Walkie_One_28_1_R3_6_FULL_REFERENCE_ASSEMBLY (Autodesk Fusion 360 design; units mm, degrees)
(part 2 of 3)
sketch "Sketch14" plane through (0, 0, -2) normal (0, 0, -1) x axis (-1, 0, 0)
  line L1 (10.455, -25.788) -> (10.455, -8.688)
  line L2 (-10.455, -25.788) -> (10.455, -25.788)
  line L3 (-10.455, -8.688) -> (-10.455, -25.788)
  line L4 (10.455, -8.688) -> (-10.455, -8.688)
  line L5 (15.947, 53.3392) -> (13.0996, 53.2792)
  line L6 (13.4186, 23) -> (16.2667, 23)
  line L7 (-13.7036, 52.7142) -> (-16.5511, 52.6542)
  line L8 (-16.2386, 23) -> (-13.3905, 23)
  line L9 (20, -67) -> (-20, -67)
  line L10 (32, 55) -> (32, -55)
  line L11 (-20, 67) -> (20, 67)
  line L12 (-32, -55) -> (-32, 55)
  circle C1 centre (0.0141, 38) radius 18
  circle C2 centre (0.0009, 14.35) radius 1.55
  circle C3 centre (-0.001, 61.6494) radius 1.5503
  arc A1 centre (0.0141, 38) radius 22.1167 clockwise from (15.947, 53.3392) to (16.2667, 23)
  arc A2 centre (0.0141, 38) radius 20.1167 clockwise from (13.0996, 53.2792) to (13.4186, 23)
  arc A3 centre (0.0141, 38) radius 20.1167 clockwise from (-13.3905, 23) to (-13.7036, 52.7142)
  arc A4 centre (0.0141, 38) radius 22.1167 clockwise from (-16.2386, 23) to (-16.5511, 52.6542)
  arc A5 centre (-20, -55) radius 12 clockwise from (-20, -67) to (-32, -55)
  arc A6 centre (20, -55) radius 12 clockwise from (32, -55) to (20, -67)
  arc A7 centre (20, 55) radius 12 clockwise from (20, 67) to (32, 55)
  arc A8 centre (-20, 55) radius 12 clockwise from (-32, 55) to (-20, 67)
  circle C4 centre (0, -47) radius 13.55
  circle C5 centre (0, 0) radius 2.4048
  circle C6 centre (22, -50) radius 3.0946
  circle C7 centre (-21.5, 24) radius 3
  circle C8 centre (-26.2206, 8.558) radius 3
  dimension "d195" diameter C7 = 6
  dimension "d196" diameter C8 = 6
extrude "Extrude13" add sketch "Sketch14" profile of C6 C7 C8 along normal blind 11
sketch "Sketch6" plane through (0, 0, -14.4) normal (0, 0, 1) x axis (1, 0, 0)
  line L1 (16.9755, 27.26) -> (26.9755, 27.26)
  line L2 (16.9755, 23.96) -> (16.9755, 27.26)
  line L3 (26.9755, 23.96) -> (16.9755, 23.96)
  line L4 (26.9755, 27.26) -> (26.9755, 23.96)
  line L5 (21.3, 23.96) -> (16.9755, 23.96)
  line L6 (21.3, 24.8) -> (21.3, 23.96)
  line L7 (16.9755, 24.8) -> (21.3, 24.8)
  line L8 (16.9755, 23.96) -> (16.9755, 24.8)
  point P4 (16.9755, 23.96)
  point P6 (16.9755, 23.96)
  horizontal L5
  vertical L6
  horizontal L7
  vertical L8
  coincident P4 P6
extrude "Extrude7" cut sketch "Sketch6" profile of L2 L3 L5 L6 L7 L8 against normal blind 1
sketch "Sketch7" plane through (0, 0, -22) normal (0, 0, 1) x axis (1, 0, 0)
  line L1 (22.6952, 6.5) -> (32, 6.5)
  line L2 (22.6952, 10.5) -> (22.6952, 6.5)
  line L3 (32, 10.5) -> (22.6952, 10.5)
  line L4 (32, 55) -> (32, 10.5)
  curve K1 (20, 67) -> (32, 55)
  line L5 (-20, 67) -> (20, 67)
  curve K2 (-32, 55) -> (-20, 67)
  line L6 (-32, -55) -> (-32, 55)
  curve K3 (-20, -67) -> (-32, -55)
  line L7 (20, -67) -> (-20, -67)
  curve K4 (32, -55) -> (20, -67)
  line L8 (32, 6.5) -> (32, -55)
  line L9 (-26.9755, -50.04) -> (-26.9755, -58.04)
  line L10 (-16.9755, -50.04) -> (-26.9755, -50.04)
  line L11 (-16.9755, -58.04) -> (-16.9755, -50.04)
  line L12 (-26.9755, -58.04) -> (-16.9755, -58.04)
  line L13 (26.9755, 31.96) -> (16.9755, 31.96)
  line L14 (26.9755, 23.96) -> (26.9755, 31.96)
  line L15 (16.9755, 23.96) -> (26.9755, 23.96)
  line L16 (16.9755, 31.96) -> (16.9755, 23.96)
  line L17 (20, 73) -> (-20, 73)
  line L18 (-20, -73) -> (20, -73)
  line L19 (-38, 55) -> (-38, -55)
  line L20 (38, -55) -> (38, -15.5)
  line L21 (31, 66) -> (-31, 66)
  line L22 (31, -66) -> (31, 66)
  line L23 (-31, -66) -> (31, -66)
  line L24 (-31, 66) -> (-31, -66)
  line L25 (38, 32.5) -> (38, 55)
  circle C1 centre (-31, 66) radius 1.5
  circle C2 centre (31, 66) radius 1.5
  circle C3 centre (31, -66) radius 1.5
  circle C4 centre (-31, -66) radius 1.5
  point P22 (-31, 66)
  point P31 (-31, 66)
  point P32 (31, 66)
  point P35 (31, 66)
  point P33 (31, -66)
  point P36 (31, -66)
  point P34 (-31, -66)
  point P37 (-31, -66)
  horizontal L21
  vertical L22
  horizontal L23
  vertical L24
  coincident P22 P31
  coincident P32 P35
  coincident P33 P36
  coincident P34 P37
  dimension "d201" diameter C1 = 3
  dimension "d202" distance P22 L17 = 7
  dimension "d203" distance P22 L19 = 7
  dimension "d210" diameter C2 = 3
  dimension "d211" diameter C4 = 3
  dimension "d212" diameter C3 = 3
  dimension "d225" distance L22 L25 = 7
  dimension "d226" distance L18 L23 = 7
position "Position6"
sketch "Sketch6" plane through (-41.9, 0, 0) normal (-1, 0, 0) x axis (0, 0, 1)
  line L1 (-12.1, 39) -> (-11.9, 39)
  line L2 (-18, -9.1) -> (-18, 33.1)
  line L3 (-11.9, -15) -> (-12.1, -15)
  line L4 (-6, 33.1) -> (-6, -9.1)
  line L5 (-12.1, 39) -> (-11.9, 39)
  line L6 (-18, -9.1) -> (-18, 33.1)
  line L7 (-11.9, -15) -> (-12.1, -15)
  line L8 (-6, 33.1) -> (-6, -9.1)
  line L9 (-18.3, -9.1) -> (-18.3, 33.1)
  line L10 (-11.9, -15.3) -> (-12.1, -15.3)
  line L11 (-5.7, 33.1) -> (-5.7, -9.1)
  line L12 (-12.1, 39.3) -> (-11.9, 39.3)
  arc A1 centre (-11.9, 33.1) radius 5.9 clockwise from (-11.9, 39) to (-6, 33.1)
  arc A2 centre (-12.1, 33.1) radius 5.9 clockwise from (-18, 33.1) to (-12.1, 39)
  arc A3 centre (-12.1, -9.1) radius 5.9 clockwise from (-12.1, -15) to (-18, -9.1)
  arc A4 centre (-11.9, -9.1) radius 5.9 clockwise from (-6, -9.1) to (-11.9, -15)
  arc A5 centre (-12.1, 33.1) radius 5.9 clockwise from (-18, 33.1) to (-12.1, 39)
  arc A6 centre (-12.1, -9.1) radius 5.9 clockwise from (-12.1, -15) to (-18, -9.1)
  arc A7 centre (-11.9, -9.1) radius 5.9 clockwise from (-6, -9.1) to (-11.9, -15)
  arc A8 centre (-11.9, 33.1) radius 5.9 clockwise from (-11.9, 39) to (-6, 33.1)
  arc A9 centre (-12.1, 33.1) radius 6.2 clockwise from (-18.3, 33.1) to (-12.1, 39.3)
  arc A10 centre (-12.1, -9.1) radius 6.2 clockwise from (-12.1, -15.3) to (-18.3, -9.1)
  arc A11 centre (-11.9, -9.1) radius 6.2 clockwise from (-5.7, -9.1) to (-11.9, -15.3)
  arc A12 centre (-11.9, 33.1) radius 6.2 clockwise from (-11.9, 39.3) to (-5.7, 33.1)
  dimension "d204" distance L4 = 0
  dimension "d205" = 0.3
extrude "Extrude8" cut sketch "Sketch6" against normal blind 6
extrude "Extrude9" cut sketch "Sketch7" profile of K1 K2 K3 K4 C1 C2 C3 C4 against normal blind 10 and along normal blind 5
sketch "Sketch8" plane through (0, 0, -22) normal (0, 0, 1) x axis (1, 0, 0)
  circle C1 centre (-31, 66) radius 5.5
  circle C2 centre (31, 66) radius 5.5
  circle C3 centre (31, -66) radius 1.5
  circle C4 centre (-31, -66) radius 1.5
  circle C5 centre (-31, -66) radius 5.5
  circle C6 centre (31, -66) radius 5.5
  circle C7 centre (-31, 66) radius 1.5
  circle C8 centre (31, 66) radius 1.5
  circle C9 centre (-31, -66) radius 1.5
  circle C10 centre (31, -66) radius 1.5
  concentric C4 C5
  concentric C3 C6
  concentric C1 C7
  concentric C2 C8
  concentric C5 C9
  concentric C6 C10
  dimension "d217" diameter C1 = 11
  dimension "d218" diameter C2 = 11
  dimension "d219" diameter C6 = 11
  dimension "d220" diameter C5 = 11
  dimension "d221" diameter C7 = 3
  dimension "d222" diameter C8 = 3
  dimension "d223" diameter C9 = 3
  dimension "d224" diameter C10 = 3
extrude "Extrude10" add sketch "Sketch8" along normal blind 10
delete_face "DeleteFace2"
sketch "Sketch9" plane through (0, 0, -22) normal (0, 0, -1) x axis (-1, 0, 0)
  curve K1 (-31.1274, 69.9946) -> (-32.4946, 68.6274)
  arc A1 centre (-31, 66) radius 1.5 clockwise from (-31.8292, 67.25) to (-30.1708, 67.25)
  circle C1 centre (31, -66) radius 2.75
  circle C2 centre (-31, -66) radius 2.75
  circle C3 centre (-31, 66) radius 2.75
  circle C4 centre (31, 66) radius 2.75
  arc A2 centre (-31, 68.5) radius 1.5 clockwise from (-31.8292, 67.25) to (-32.4946, 68.6274)
  arc A3 centre (-31, 68.5) radius 1.5 clockwise from (-31.1274, 69.9946) to (-30.1708, 67.25)
  point P7 (-31, -66)
  point P10 (-31, -66)
  point P9 (-31, 66)
  point P11 (-31, 66)
  point P8 (31, 66)
  point P12 (31, 66)
  coincident P7 P10
  coincident P9 P11
  coincident P8 P12
  dimension "d229" diameter C1 = 5.5
  dimension "d230" diameter C2 = 5.5
  dimension "d231" diameter C3 = 5.5
  dimension "d232" diameter C4 = 5.5
extrude "Extrude11" cut sketch "Sketch9" profile of K1 A1 C1 C2 C3 C4 along normal blind 6 and against normal blind 2
sketch "Sketch15" plane through (0, 0, -2) normal (0, 0, -1) x axis (-1, 0, 0)
  line L1 (20, -67) -> (-20, -67)
  line L2 (32, 55) -> (32, -55)
  line L3 (-20, 67) -> (20, 67)
  line L4 (-32, -55) -> (-32, 55)
  line L5 (-13.7036, 52.7142) -> (-16.5511, 52.6542)
  line L6 (-16.2386, 23) -> (-13.3905, 23)
  line L7 (15.947, 53.3392) -> (13.0996, 53.2792)
  line L8 (13.4186, 23) -> (16.2667, 23)
  line L9 (10.455, -25.788) -> (10.455, -8.688)
  line L10 (-10.455, -25.788) -> (10.455, -25.788)
  line L11 (-10.455, -8.688) -> (-10.455, -25.788)
  line L12 (10.455, -8.688) -> (-10.455, -8.688)
  curve K1 (-33.7293, 65.6634) -> (-33.7293, 65.6634)
  curve K2 (28.5839, 67.3134) -> (28.5839, 67.3134)
  curve K3 (-33.2911, -64.479) -> (-33.2911, -64.479)
  curve K4 (28.2521, -65.8917) -> (28.2521, -65.8917)
  circle C1 centre (-26.2206, 8.558) radius 3
  circle C2 centre (0, 0) radius 2.4048
  circle C3 centre (0, -47) radius 13.55
  arc A1 centre (-20, -55) radius 12 clockwise from (-20, -67) to (-32, -55)
  arc A2 centre (20, -55) radius 12 clockwise from (32, -55) to (20, -67)
  arc A3 centre (20, 55) radius 12 clockwise from (20, 67) to (32, 55)
  arc A4 centre (-20, 55) radius 12 clockwise from (-32, 55) to (-20, 67)
  arc A5 centre (0.0141, 38) radius 20.1167 clockwise from (-13.3905, 23) to (-13.7036, 52.7142)
  arc A6 centre (0.0141, 38) radius 22.1167 clockwise from (-16.2386, 23) to (-16.5511, 52.6542)
  arc A7 centre (0.0141, 38) radius 22.1167 clockwise from (15.947, 53.3392) to (16.2667, 23)
  arc A8 centre (0.0141, 38) radius 20.1167 clockwise from (13.0996, 53.2792) to (13.4186, 23)
  circle C4 centre (-0.001, 61.6494) radius 1.5503
  circle C5 centre (0.0009, 14.35) radius 1.55
  circle C6 centre (0.0141, 38) radius 18
  circle C7 centre (-21.5, 24) radius 3
  circle C8 centre (22, -50) radius 3.0946
  circle C9 centre (-31, 66) radius 3.5
  circle C10 centre (31, 66) radius 3.5
  circle C11 centre (-31, -66) radius 3.5
  circle C12 centre (31, -66) radius 3.5
  circle C13 centre (-31, 66) radius 1
  circle C14 centre (31, 66) radius 1
  circle C15 centre (-31, -66) radius 1
  circle C16 centre (31, -66) radius 1
  concentric C9 C13
  concentric C10 C14
  concentric C11 C15
  concentric C12 C16
  dimension "d237" diameter C9 = 7
  dimension "d238" diameter C10 = 7
  dimension "d239" diameter C11 = 7
  dimension "d240" diameter C12 = 7
  dimension "d241" diameter C13 = 2
  dimension "d242" diameter C14 = 2
  dimension "d243" diameter C15 = 2
  dimension "d244" diameter C16 = 2
extrude "Extrude15" add sketch "Sketch15" profile of K1 K2 K3 K4 C9 C10 C11 C12 C13 C14 C15 C16 along normal blind 10
delete_face "DeleteFace1"
sketch "Sketch11" plane through (0, 0, -12) normal (0, 0, 1) x axis (1, 0, 0)
  line L1 (-40, 39.3) -> (-40, 55)
  line L2 (-38, 55) -> (-38, 39.3)
  line L3 (38, 32.5) -> (38, 55)
  line L4 (40, 55) -> (40, 32.5)
  line L5 (-35.1621, -62.4046) -> (-34.285, -64.2974)
  line L6 (-26.9184, -69.6865) -> (-29.2974, -69.285)
  line L7 (26.9184, -69.6865) -> (29.2974, -69.285)
  line L8 (35.1621, -62.4046) -> (34.285, -64.2974)
  line L9 (27.3105, 70.0789) -> (29.2974, 69.285)
  line L10 (35.0789, 62.3105) -> (34.285, 64.2974)
  line L11 (-27.3105, 70.0789) -> (-29.2974, 69.285)
  line L12 (-35.0789, 62.3105) -> (-34.285, 64.2974)
  line L13 (-20, 75) -> (20, 75)
  line L14 (-38, 39.3) -> (-40, 39.3)
  line L15 (20, 73) -> (-20, 73)
  line L16 (40, 32.5) -> (38, 32.5)
  arc A1 centre (-31, 66) radius 5.5 clockwise from (-28.4692, 70.8831) to (-35.8831, 63.4692)
  arc A2 centre (31, 66) radius 5.5 clockwise from (35.8831, 63.4692) to (28.4692, 70.8831)
  arc A3 centre (31, -66) radius 5.5 clockwise from (28.4692, -70.8831) to (35.8831, -63.4692)
  arc A4 centre (-31, -66) radius 5.5 clockwise from (-35.8831, -63.4692) to (-28.4692, -70.8831)
  arc A5 centre (31, -66) radius 3.7 clockwise from (29.2974, -69.285) to (34.285, -64.2974)
  arc A6 centre (-31, -66) radius 3.7 clockwise from (-34.285, -64.2974) to (-29.2974, -69.285)
  circle C1 centre (-31, 66) radius 1.5
  arc A7 centre (20, 55) radius 20 clockwise from (20, 75) to (40, 55)
  arc A8 centre (-20, 55) radius 20 clockwise from (-40, 55) to (-20, 75)
  arc A9 centre (-20, 55) radius 18 clockwise from (-38, 55) to (-35.8831, 63.4692)
  arc A10 centre (-31, 66) radius 5.5 clockwise from (-28.4692, 70.8831) to (-35.8831, 63.4692)
  arc A11 centre (-20, 55) radius 18 clockwise from (-28.4692, 70.8831) to (-20, 73)
  arc A12 centre (20, 55) radius 18 clockwise from (20, 73) to (28.4692, 70.8831)
  arc A13 centre (31, 66) radius 5.5 clockwise from (35.8831, 63.4692) to (28.4692, 70.8831)
  arc A14 centre (20, 55) radius 18 clockwise from (35.8831, 63.4692) to (38, 55)
  circle C2 centre (31, 66) radius 1.5
  arc A15 centre (31, 66) radius 3.7 clockwise from (34.285, 64.2974) to (29.2974, 69.285)
  arc A16 centre (-31, 66) radius 3.7 clockwise from (-29.2974, 69.285) to (-34.285, 64.2974)
  point P32 (-26.9184, -69.6865)
  point P33 (-35.1621, -62.4046)
  point P38 (35.1621, -62.4046)
  point P39 (26.9184, -69.6865)
  coincident A4 P32
  coincident A4 P33
  coincident A3 P38
  coincident A3 P39
  dimension "d250" = -1.8
  dimension "d251" = -1.8
  dimension "d398" = -1.8
  dimension "d399" = -1.8
extrude "Extrude12" add sketch "Sketch11" profile of A1 A2 A3 A4 A5 A6 L5 L6 L7 L8 L9 L10 L11 L12 along normal blind 2
fillet "Fillet3" radius 0.5
offset_faces "OffsetFaces1" distance 2
offset_faces "OffsetFaces2" distance 2
fillet "Fillet3" radius 2
sketch "Sketch16" plane through (0, 0, -5) normal (0, 0, -1) x axis (-1, 0, 0)
  line L1 (-8.455, -23.788) -> (8.455, -23.788)
  line L2 (-8.455, -10.688) -> (-8.455, -23.788)
  line L3 (8.455, -10.688) -> (-8.455, -10.688)
  line L4 (8.455, -23.788) -> (8.455, -10.688)
  line L5 (-10.455, -8.688) -> (10.455, -8.688)
  line L6 (-12.455, -23.788) -> (-12.455, -10.688)
  line L7 (10.455, -25.788) -> (-10.455, -25.788)
  line L8 (12.455, -10.688) -> (12.455, -23.788)
  arc A1 centre (10.455, -10.688) radius 2 clockwise from (10.455, -8.688) to (12.455, -10.688)
  arc A2 centre (-10.455, -10.688) radius 2 clockwise from (-12.455, -10.688) to (-10.455, -8.688)
  arc A3 centre (-10.455, -23.788) radius 2 clockwise from (-10.455, -25.788) to (-12.455, -23.788)
  arc A4 centre (10.455, -23.788) radius 2 clockwise from (12.455, -23.788) to (10.455, -25.788)
  circle C1 centre (-9.955, -17.238) radius 1
  circle C2 centre (9.955, -17.238) radius 1
  point P18 (-9.955, -17.238)
  point P19 (9.955, -17.238)
  dimension "d260" diameter C1 = 2
  dimension "d261" distance L2 P18 = 1.5
  dimension "d262" diameter C2 = 2
  dimension "d263" distance L4 P19 = 1.5
extrude "Extrude16" cut sketch "Sketch16" profile of C1 C2 against normal blind 3
position "Position7"
sketch "Sketch7" plane through (0, 0, -2) normal (0, 0, -1) x axis (-1, 0, 0)
  line L1 (20, -67) -> (-20, -67)
  line L2 (32, 55) -> (32, -55)
  line L3 (-20, 67) -> (20, 67)
  line L4 (-32, -55) -> (-32, 55)
  line L5 (-13.7036, 52.7142) -> (-16.5511, 52.6542)
  line L6 (-16.2386, 23) -> (-13.3905, 23)
  line L7 (15.947, 53.3392) -> (13.0996, 53.2792)
  line L8 (13.4186, 23) -> (16.2667, 23)
  line L9 (12.455, -23.788) -> (12.455, -10.688)
  line L10 (-10.455, -25.788) -> (10.455, -25.788)
  line L11 (-12.455, -10.688) -> (-12.455, -23.788)
  line L12 (10.455, -8.688) -> (-10.455, -8.688)
  line L13 (18.542, -42) -> (-18.5381, -42)
  line L14 (18.542, -52) -> (18.542, -42)
  line L15 (-18.5381, -52) -> (18.542, -52)
  line L16 (-18.5381, -42) -> (-18.5381, -52)
  line L17 (-13.5381, -55) -> (-13.5381, -46.4331)
  line L18 (13.542, -56) -> (13.542, -47.467)
  circle C1 centre (-26.2206, 8.558) radius 3
  circle C2 centre (0, 0) radius 2.4048
  circle C3 centre (0, -47) radius 13.55
  arc A1 centre (-20, -55) radius 12 clockwise from (-20, -67) to (-32, -55)
  arc A2 centre (20, -55) radius 12 clockwise from (32, -55) to (20, -67)
  arc A3 centre (20, 55) radius 12 clockwise from (20, 67) to (32, 55)
  arc A4 centre (-20, 55) radius 12 clockwise from (-32, 55) to (-20, 67)
  arc A5 centre (0.0141, 38) radius 20.1167 clockwise from (-13.3905, 23) to (-13.7036, 52.7142)
  arc A6 centre (0.0141, 38) radius 22.1167 clockwise from (-16.2386, 23) to (-16.5511, 52.6542)
  arc A7 centre (0.0141, 38) radius 22.1167 clockwise from (15.947, 53.3392) to (16.2667, 23)
  arc A8 centre (0.0141, 38) radius 20.1167 clockwise from (13.0996, 53.2792) to (13.4186, 23)
  circle C4 centre (-0.001, 61.6494) radius 1.5503
  circle C5 centre (0.0009, 14.35) radius 1.55
  circle C6 centre (0.0141, 38) radius 18
  arc A9 centre (10.455, -23.788) radius 2 clockwise from (12.455, -23.788) to (10.455, -25.788)
  arc A10 centre (-10.455, -23.788) radius 2 clockwise from (-10.455, -25.788) to (-12.455, -23.788)
  arc A11 centre (-10.455, -10.688) radius 2 clockwise from (-12.455, -10.688) to (-10.455, -8.688)
  arc A12 centre (10.455, -10.688) radius 2 clockwise from (10.455, -8.688) to (12.455, -10.688)
  circle C7 centre (-21.5, 24) radius 3
  circle C8 centre (22, -50) radius 3.0946
  point P46 (-13.5381, -46.4331)
  point P48 (13.542, -47.467)
  horizontal L13
  vertical L14
  horizontal L15
  vertical L16
  coincident C3 P46
  perpendicular L15 L17
  coincident C3 P48
  perpendicular L15 L18
  dimension "d266" distance L16 L17 = 5
  dimension "d267" distance L14 L18 = 5
sketch "Sketch17" plane through (0, 0, -2) normal (0, 0, -1) x axis (-1, 0, 0)
  line L1 (20, -67) -> (-20, -67)
  line L2 (32, 55) -> (32, -55)
  line L3 (-20, 67) -> (20, 67)
  line L4 (-32, -55) -> (-32, 55)
  line L5 (-13.7036, 52.7142) -> (-16.5511, 52.6542)
  line L6 (-16.2386, 23) -> (-13.3905, 23)
  line L7 (15.947, 53.3392) -> (13.0996, 53.2792)
  line L8 (13.4186, 23) -> (16.2667, 23)
  line L9 (12.455, -23.788) -> (12.455, -10.688)
  line L10 (-10.455, -25.788) -> (10.455, -25.788)
  line L11 (-12.455, -10.688) -> (-12.455, -23.788)
  line L12 (10.455, -8.688) -> (-10.455, -8.688)
  line L13 (-18.5, -56.5) -> (18.5, -56.5)
  line L14 (-18.5, -37.5) -> (-18.5, -56.5)
  line L15 (18.5, -37.5) -> (-18.5, -37.5)
  line L16 (18.5, -56.5) -> (18.5, -37.5)
  line L17 (-18.5, -37.5) -> (18.5, -56.5)
  line L18 (18.5, -37.5) -> (-18.5, -56.5)
  circle C1 centre (-26.2206, 8.558) radius 3
  circle C2 centre (0, 0) radius 2.4048
  circle C3 centre (0, -47) radius 13.55
  arc A1 centre (-20, -55) radius 12 clockwise from (-20, -67) to (-32, -55)
  arc A2 centre (20, -55) radius 12 clockwise from (32, -55) to (20, -67)
  arc A3 centre (20, 55) radius 12 clockwise from (20, 67) to (32, 55)
  arc A4 centre (-20, 55) radius 12 clockwise from (-32, 55) to (-20, 67)
  arc A5 centre (0.0141, 38) radius 20.1167 clockwise from (-13.3905, 23) to (-13.7036, 52.7142)
  arc A6 centre (0.0141, 38) radius 22.1167 clockwise from (-16.2386, 23) to (-16.5511, 52.6542)
  arc A7 centre (0.0141, 38) radius 22.1167 clockwise from (15.947, 53.3392) to (16.2667, 23)
  arc A8 centre (0.0141, 38) radius 20.1167 clockwise from (13.0996, 53.2792) to (13.4186, 23)
  circle C4 centre (-0.001, 61.6494) radius 1.5503
  circle C5 centre (0.0009, 14.35) radius 1.55
  circle C6 centre (0.0141, 38) radius 18
  arc A9 centre (10.455, -23.788) radius 2 clockwise from (12.455, -23.788) to (10.455, -25.788)
  arc A10 centre (-10.455, -23.788) radius 2 clockwise from (-10.455, -25.788) to (-12.455, -23.788)
  arc A11 centre (-10.455, -10.688) radius 2 clockwise from (-12.455, -10.688) to (-10.455, -8.688)
  arc A12 centre (10.455, -10.688) radius 2 clockwise from (10.455, -8.688) to (12.455, -10.688)
  circle C7 centre (-21.5, 24) radius 3
  circle C8 centre (22, -50) radius 3.0946
  circle C9 centre (-16, -54) radius 1
  circle C10 centre (-16, -54) radius 3.25
  circle C11 centre (16, -40) radius 1
  circle C12 centre (16, -40) radius 3.25
  point P46 (0, -47)
  point P4 (0, -47)
  point P44 (-18.5, -37.5)
  point P45 (18.5, -37.5)
  point P43 (-18.5, -56.5)
  point P48 (-16, -54)
  point P49 (16, -40)
  horizontal L13
  perpendicular L13 L14
  parallel L13 L15
  parallel L14 L16
  coincident L17 P46
  coincident L18 P46
  coincident P4 P46
  concentric C9 C10
  concentric C11 C12
  dimension "d268" distance P44 P45 = 37
  dimension "d269" distance P43 P44 = 19
  dimension "d270" diameter C9 = 2
  dimension "d271" diameter C10 = 6.5
  dimension "d272" distance L14 P48 = 2.5
  dimension "d274" diameter C11 = 2
  dimension "d275" diameter C12 = 6.5
  dimension "d277" distance L16 P49 = 2.5
  dimension "d278" distance L15 P49 = 2.5
  dimension "d279" distance L13 P48 = 2.5
extrude "Extrude17" add sketch "Sketch17" profile of L13 L14 L15 L16 C9 C10 C11 C12 along normal blind 5
sketch "Sketch8" plane through (0, 0, -7) normal (0, 0, -1) x axis (-1, 0, 0)
  line L1 (-21, -59) -> (-9, -59)
  line L2 (-21, -42) -> (-21, -59)
  line L3 (18.8, -35) -> (9, -35)
  line L4 (-6.9857, -42) -> (6, -51.5684)
  line L5 (9, -42) -> (9, -35)
  line L6 (-21, -42) -> (9, -42)
  line L7 (6, -41) -> (6, -53)
  line L8 (-9, -51) -> (-9, -59)
  line L9 (15, -51) -> (-9, -51)
  line L10 (-6, -53) -> (-6, -41)
  line L11 (21, -35) -> (18.8, -35)
  line L12 (21, -45) -> (21, -35)
  line L13 (18.8, -45) -> (21, -45)
  line L14 (15, -51) -> (18.8, -45)
  circle C1 centre (-16, -54) radius 1
  circle C2 centre (-16, -54) radius 3.25
  circle C3 centre (16, -40) radius 1
  point P5 (-0.2, -47)
  point P16 (-6.9857, -42)
  point P17 (6, -51.5684)
  point P6 (16, -40)
  point P18 (21, -35)
  point P19 (21, -45)
  point P2 (-16, -54)
  horizontal L1
  perpendicular L1 L2
  parallel L1 L3
  coincident L4 P5
  vertical L5
  horizontal L6
  vertical L8
  horizontal L9
  coincident L6 P16
  coincident L7 P17
  horizontal L11
  vertical L12
  horizontal L13
  dimension "d282" distance L3 P6 = 5
  dimension "d284" distance L5 L7 = 3
  dimension "d285" distance L8 L10 = 3
  dimension "d288" distance P18 P19 = 10
  dimension "d289" distance P2 L1 = 5
  dimension "d290" distance P2 L2 = 5
  dimension "d291" distance P6 L12 = 5
extrude "Extrude1" new body sketch "Sketch8" profile of C1 C2 L1 L2 L3 C3 L5 L6 L7 L8 L9 L10 along normal blind 4
fillet "Fillet1" radius 2
sketch "Sketch1" plane through (0, 0, -11) normal (0, 0, -1) x axis (-1, 0, 0)
  line L1 (-21, -57) -> (-21, -44)
  line L2 (-11, -59) -> (-19, -59)
  line L3 (-9, -53) -> (-9, -57)
  line L4 (13.8993, -51) -> (-7, -51)
  line L5 (18.8, -45) -> (15.5889, -50.0701)
  line L6 (19, -45) -> (18.8, -45)
  line L7 (21, -37) -> (21, -43)
  line L8 (11, -35) -> (19, -35)
  line L9 (9, -40) -> (9, -37)
  line L10 (-19, -42) -> (7, -42)
  arc A1 centre (-19, -44) radius 2 clockwise from (-21, -44) to (-19, -42)
  arc A2 centre (-19, -57) radius 2 clockwise from (-19, -59) to (-21, -57)
  arc A3 centre (-11, -57) radius 2 clockwise from (-9, -57) to (-11, -59)
  arc A4 centre (-7, -53) radius 2 clockwise from (-9, -53) to (-7, -51)
  arc A5 centre (13.8993, -49) radius 2 clockwise from (15.5889, -50.0701) to (13.8993, -51)
  arc A6 centre (19, -43) radius 2 clockwise from (21, -43) to (19, -45)
  arc A7 centre (19, -37) radius 2 clockwise from (19, -35) to (21, -37)
  arc A8 centre (11, -37) radius 2 clockwise from (9, -37) to (11, -35)
  arc A9 centre (7, -40) radius 2 clockwise from (9, -40) to (7, -42)
  circle C1 centre (-16, -54) radius 3.25
  circle C2 centre (16, -40) radius 3.25
  circle C3 centre (-16, -54) radius 1.5
  circle C4 centre (16, -40) radius 1.5
  concentric C1 C3
  concentric C2 C4
  dimension "d294" diameter C4 = 3
  dimension "d295" diameter C3 = 3
extrude "Extrude2" cut sketch "Sketch1" profile of C3 C4 against normal blind 7
sketch "Sketch2" plane through (0, 0, -11) normal (0, 0, -1) x axis (-1, 0, 0)
  line L1 (-21, -57) -> (-21, -44)
  line L2 (-11, -59) -> (-19, -59)
  line L3 (-9, -53) -> (-9, -57)
  line L4 (13.8993, -51) -> (-7, -51)
  line L5 (18.8, -45) -> (15.5889, -50.0701)
  line L6 (19, -45) -> (18.8, -45)
  line L7 (21, -37) -> (21, -43)
  line L8 (11, -35) -> (19, -35)
  line L9 (9, -40) -> (9, -37)
  line L10 (-19, -42) -> (7, -42)
  circle C1 centre (-16, -54) radius 1.5
  circle C2 centre (16, -40) radius 1.5
  arc A1 centre (-19, -44) radius 2 clockwise from (-21, -44) to (-19, -42)
  arc A2 centre (-19, -57) radius 2 clockwise from (-19, -59) to (-21, -57)
  arc A3 centre (-11, -57) radius 2 clockwise from (-9, -57) to (-11, -59)
  arc A4 centre (-7, -53) radius 2 clockwise from (-9, -53) to (-7, -51)
  arc A5 centre (13.8993, -49) radius 2 clockwise from (15.5889, -50.0701) to (13.8993, -51)
  arc A6 centre (19, -43) radius 2 clockwise from (21, -43) to (19, -45)
  arc A7 centre (19, -37) radius 2 clockwise from (19, -35) to (21, -37)
  arc A8 centre (11, -37) radius 2 clockwise from (9, -37) to (11, -35)
  arc A9 centre (7, -40) radius 2 clockwise from (9, -40) to (7, -42)
  circle C3 centre (-16, -54) radius 2.75
  circle C4 centre (16, -40) radius 2.75
  concentric C1 C3
  concentric C2 C4
  dimension "d298" diameter C4 = 5.5
  dimension "d299" diameter C3 = 5.5
extrude "Extrude3" cut sketch "Sketch2" profile of C1 C2 C3 C4 against normal blind 2.5
sketch "Sketch9" plane through (0, 0, -2) normal (0, 0, -1) x axis (-1, 0, 0)
  line L1 (20, -67) -> (-20, -67)
  line L2 (32, 55) -> (32, -55)
  line L3 (-20, 67) -> (20, 67)
  line L4 (-32, -55) -> (-32, 55)
  line L5 (-13.7036, 52.7142) -> (-16.5511, 52.6542)
  line L6 (-16.2386, 23) -> (-13.3905, 23)
  line L7 (15.947, 53.3392) -> (13.0996, 53.2792)
  line L8 (13.4186, 23) -> (16.2667, 23)
  line L9 (12.455, -23.788) -> (12.455, -10.688)
  line L10 (-10.455, -25.788) -> (10.455, -25.788)
  line L11 (-12.455, -10.688) -> (-12.455, -23.788)
  line L12 (10.455, -8.688) -> (-10.455, -8.688)
  circle C1 centre (-16, -54) radius 3.25
  circle C2 centre (-26.2206, 8.558) radius 3
  circle C3 centre (0, 0) radius 2.4048
  circle C4 centre (0, -47) radius 13.55
  arc A1 centre (-20, -55) radius 12 clockwise from (-20, -67) to (-32, -55)
  arc A2 centre (20, -55) radius 12 clockwise from (32, -55) to (20, -67)
  arc A3 centre (20, 55) radius 12 clockwise from (20, 67) to (32, 55)
  arc A4 centre (-20, 55) radius 12 clockwise from (-32, 55) to (-20, 67)
  arc A5 centre (0.0141, 38) radius 20.1167 clockwise from (-13.3905, 23) to (-13.7036, 52.7142)
  arc A6 centre (0.0141, 38) radius 22.1167 clockwise from (-16.2386, 23) to (-16.5511, 52.6542)
  arc A7 centre (0.0141, 38) radius 22.1167 clockwise from (15.947, 53.3392) to (16.2667, 23)
  arc A8 centre (0.0141, 38) radius 20.1167 clockwise from (13.0996, 53.2792) to (13.4186, 23)
  circle C5 centre (-0.001, 61.6494) radius 1.5503
  circle C6 centre (0.0009, 14.35) radius 1.55
  circle C7 centre (0.0141, 38) radius 18
  arc A9 centre (10.455, -23.788) radius 2 clockwise from (12.455, -23.788) to (10.455, -25.788)
  arc A10 centre (-10.455, -23.788) radius 2 clockwise from (-10.455, -25.788) to (-12.455, -23.788)
  arc A11 centre (-10.455, -10.688) radius 2 clockwise from (-12.455, -10.688) to (-10.455, -8.688)
  arc A12 centre (10.455, -10.688) radius 2 clockwise from (10.455, -8.688) to (12.455, -10.688)
  circle C8 centre (-21.5, 24) radius 3
  circle C9 centre (22, -50) radius 3.0946
  circle C10 centre (16, -40) radius 3.25
sketch "Sketch18" plane through (0, 0, -2) normal (0, 0, -1) x axis (-1, 0, 0)
  line L1 (20, -67) -> (-20, -67)
  line L2 (32, 55) -> (32, -55)
  line L3 (-20, 67) -> (20, 67)
  line L4 (-32, -55) -> (-32, 55)
  line L5 (-13.7036, 52.7142) -> (-16.5511, 52.6542)
  line L6 (-16.2386, 23) -> (-13.3905, 23)
  line L7 (15.947, 53.3392) -> (13.0996, 53.2792)
  line L8 (13.4186, 23) -> (16.2667, 23)
  line L9 (12.455, -23.788) -> (12.455, -10.688)
  line L10 (-10.455, -25.788) -> (10.455, -25.788)
  line L11 (-12.455, -10.688) -> (-12.455, -23.788)
  line L12 (10.455, -8.688) -> (-10.455, -8.688)
  line L13 (-26.7827, 25) -> (-37.7827, 25)
  line L14 (-26.7827, 21) -> (-26.7827, 25)
  line L15 (-37.7827, 21) -> (-26.7827, 21)
  line L16 (-37.7827, 25) -> (-37.7827, 21)
  line L17 (-33.9653, -8) -> (-33.9653, 19)
  line L18 (-50.0702, 5.5) -> (-34, 5.5)
  line L19 (-37.7827, -4) -> (-26.671, -4)
  line L20 (-37.7827, -8) -> (-37.7827, -4)
  line L21 (-26.7827, -8) -> (-37.7827, -8)
  line L22 (-26.671, -4) -> (-26.7827, -8)
  line L23 (-30.4, 25.8) -> (-33.9, 25.8)
  line L24 (-33.9, 20.2) -> (-30.4, 20.2)
  line L25 (26.5417, 14) -> (37.5417, 14)
  line L26 (26.5417, 10) -> (26.5417, 14)
  line L27 (37.5417, 10) -> (26.5417, 10)
  line L28 (37.5417, 14) -> (37.5417, 10)
  line L29 (-37.5, 20) -> (-37.5, 26)
  line L30 (37.4, 15) -> (37.4, 9)
  line L31 (33.8, 14.8) -> (30.3, 14.8)
  line L32 (-37.7827, 19) -> (-37.7827, 27)
  line L33 (37.5417, 33.1) -> (37.5417, -9.1)
  line L34 (-37.7827, -10) -> (-37.7827, -2)
  circle C1 centre (-16, -54) radius 3.25
  circle C2 centre (-26.2206, 8.558) radius 3
  circle C3 centre (0, 0) radius 2.4048
  circle C4 centre (0, -47) radius 13.55
  arc A1 centre (-20, -55) radius 12 clockwise from (-20, -67) to (-32, -55)
  arc A2 centre (20, -55) radius 12 clockwise from (32, -55) to (20, -67)
  arc A3 centre (20, 55) radius 12 clockwise from (20, 67) to (32, 55)
  arc A4 centre (-20, 55) radius 12 clockwise from (-32, 55) to (-20, 67)
  arc A5 centre (0.0141, 38) radius 20.1167 clockwise from (-13.3905, 23) to (-13.7036, 52.7142)
  arc A6 centre (0.0141, 38) radius 22.1167 clockwise from (-16.2386, 23) to (-16.5511, 52.6542)
  arc A7 centre (0.0141, 38) radius 22.1167 clockwise from (15.947, 53.3392) to (16.2667, 23)
  arc A8 centre (0.0141, 38) radius 20.1167 clockwise from (13.0996, 53.2792) to (13.4186, 23)
  circle C5 centre (-0.001, 61.6494) radius 1.5503
  circle C6 centre (0.0009, 14.35) radius 1.55
  circle C7 centre (0.0141, 38) radius 18
  arc A9 centre (10.455, -23.788) radius 2 clockwise from (12.455, -23.788) to (10.455, -25.788)
  arc A10 centre (-10.455, -23.788) radius 2 clockwise from (-10.455, -25.788) to (-12.455, -23.788)
  arc A11 centre (-10.455, -10.688) radius 2 clockwise from (-12.455, -10.688) to (-10.455, -8.688)
  arc A12 centre (10.455, -10.688) radius 2 clockwise from (10.455, -8.688) to (12.455, -10.688)
  circle C8 centre (-21.5, 24) radius 3
  circle C9 centre (22, -50) radius 3.0946
  circle C10 centre (16, -40) radius 3.25
  point P44 (-37.7827, 25)
  point P47 (-37.7827, 21)
  point P53 (-37.7827, -4)
  point P54 (-37.7827, -8)
  point P45 (-26.7827, 25)
  point P55 (-26.7827, -8)
  point P60 (37.5417, 14)
  point P61 (26.5417, 14)
  point P63 (37.5417, 10)
  horizontal L13
  vertical L14
  horizontal L15
  vertical L16
  parallel L14 L17
  horizontal L18
  horizontal L21
  vertical L20
  horizontal L25
  vertical L26
  horizontal L27
  vertical L28
  collinear L20 L34
  collinear L16 L32
  collinear L28 L33
  dimension "d304" distance L15 L19 = 25 (= "29 mm - 4 mm")
  dimension "d305" distance P44 P47 = 4
  dimension "d306" distance L13 L23 = 0.8
  dimension "d307" distance P53 P54 = 4
  dimension "d310" distance P44 P45 = 11
  dimension "d311" distance P54 P55 = 11
  dimension "d312" distance P60 P61 = 11
  dimension "d313" distance P60 P63 = 4
  dimension "d315" distance L25 L31 = 0.8
extrude "Extrude18" add sketch "Sketch18" profile of L2 L4 L13 L14 L15 L16 L19 L20 L21 L22 L25 L26 L27 L28 along normal blind 7
sketch "Sketch19" plane through (0, 0, -9) normal (0, 0, -1) x axis (-1, 0, 0)
  line L1 (-26.671, -4) -> (-26.7827, -8)
  line L2 (-37.7827, -4) -> (-26.671, -4)
  line L3 (-37.7827, -8) -> (-37.7827, -4)
  line L4 (-26.7827, -8) -> (-37.7827, -8)
  line L5 (-33.4, -4) -> (-26.671, -4)
  line L6 (-33.4, -8) -> (-33.4, -4)
  line L7 (-26.671, -8) -> (-33.4, -8)
  line L8 (-26.671, -4) -> (-26.671, -8)
  line L9 (-33.9, -3) -> (-33.9, -9)
  line L10 (-33.9, 26) -> (-33.9, 20)
  line L11 (33.8, 9) -> (33.8, 15)
  line L12 (-26.7827, 25) -> (-26.7827, 21)
  line L13 (-37.7827, 25) -> (-26.7827, 25)
  line L14 (-26.7827, 21) -> (-37.7827, 21)
  line L15 (-33.4, 21) -> (-26.7827, 21)
  line L16 (-33.4, 25) -> (-33.4, 21)
  line L17 (-26.7827, 25) -> (-33.4, 25)
  line L18 (-26.7827, 21) -> (-26.7827, 25)
  line L19 (26.5417, 14) -> (37.5417, 14)
  line L20 (26.5417, 10) -> (26.5417, 14)
  line L21 (37.5417, 10) -> (26.5417, 10)
  line L22 (33.3, 14) -> (26.5417, 14)
  line L23 (33.3, 10) -> (33.3, 14)
  line L24 (26.5417, 10) -> (33.3, 10)
  line L25 (26.5417, 14) -> (26.5417, 10)
  point P8 (-33.4, -8)
  point P3 (-26.671, -4)
  point P6 (-26.671, -4)
  point P22 (-33.4, 25)
  point P16 (-26.7827, 21)
  point P20 (-26.7827, 21)
  point P30 (33.3, 10)
  point P25 (26.5417, 14)
  point P28 (26.5417, 14)
  horizontal L5
  vertical L6
  horizontal L7
  vertical L8
  coincident L4 P8
  coincident P3 P6
  horizontal L15
  vertical L16
  horizontal L17
  vertical L18
  coincident L13 P22
  coincident P16 P20
  horizontal L22
  vertical L23
  horizontal L24
  vertical L25
  coincident L21 P30
  coincident P25 P28
  dimension "d316" distance L6 L9 = 0.5
  dimension "d317" distance L10 L16 = 0.5
  dimension "d318" distance L11 L23 = 0.5
extrude "Extrude19" add sketch "Sketch19" profile of L1 L2 L4 L5 L6 L7 L12 L13 L14 L15 L16 L17 L18 L19 L20 L21 L22 L23 L24 L25 along normal blind 5
chamfer "Chamfer2" distance 6.5
chamfer "Chamfer3" distance 6.5
chamfer "Chamfer4" distance 6.5
sketch "Sketch10" plane through (0, 0, -2) normal (0, 0, -1) x axis (-1, 0, 0)
  line L1 (12.455, -23.788) -> (12.455, -10.688)
  line L2 (-10.455, -25.788) -> (10.455, -25.788)
  line L3 (-12.455, -10.688) -> (-12.455, -23.788)
  line L4 (10.455, -8.688) -> (-10.455, -8.688)
  line L5 (15.947, 53.3392) -> (13.0996, 53.2792)
  line L6 (13.4186, 23) -> (16.2667, 23)
  line L7 (-13.7036, 52.7142) -> (-16.5511, 52.6542)
  line L8 (-16.2386, 23) -> (-13.3905, 23)
  line L9 (32, 14) -> (26.5417, 14)
  line L10 (32, 55) -> (32, 14)
  line L11 (-20, 67) -> (20, 67)
  line L12 (-32, 25) -> (-32, 55)
  line L13 (-26.7827, 25) -> (-32, 25)
  line L14 (-26.7827, 21) -> (-26.7827, 25)
  line L15 (-32, 21) -> (-26.7827, 21)
  line L16 (-32, -4) -> (-32, 21)
  line L17 (-26.671, -4) -> (-32, -4)
  line L18 (-26.7827, -8) -> (-26.671, -4)
  line L19 (-32, -8) -> (-26.7827, -8)
  line L20 (-32, -55) -> (-32, -8)
  line L21 (20, -67) -> (-20, -67)
  line L22 (32, 10) -> (32, -55)
  line L23 (26.5417, 10) -> (32, 10)
  line L24 (26.5417, 14) -> (26.5417, 10)
  line L25 (9, -7) -> (-10, -7)
  line L26 (9, 7) -> (9, -7)
  line L27 (-10, 7) -> (9, 7)
  line L28 (-10, -7) -> (-10, 7)
  circle C1 centre (16, -40) radius 3.25
  circle C2 centre (22, -50) radius 3.0946
  circle C3 centre (-21.5, 24) radius 3
  arc A1 centre (10.455, -23.788) radius 2 clockwise from (12.455, -23.788) to (10.455, -25.788)
  arc A2 centre (-10.455, -23.788) radius 2 clockwise from (-10.455, -25.788) to (-12.455, -23.788)
  arc A3 centre (-10.455, -10.688) radius 2 clockwise from (-12.455, -10.688) to (-10.455, -8.688)
  arc A4 centre (10.455, -10.688) radius 2 clockwise from (10.455, -8.688) to (12.455, -10.688)
  circle C4 centre (0.0141, 38) radius 18
  circle C5 centre (0.0009, 14.35) radius 1.55
  circle C6 centre (-0.001, 61.6494) radius 1.5503
  arc A5 centre (0.0141, 38) radius 22.1167 clockwise from (15.947, 53.3392) to (16.2667, 23)
  arc A6 centre (0.0141, 38) radius 20.1167 clockwise from (13.0996, 53.2792) to (13.4186, 23)
  arc A7 centre (0.0141, 38) radius 20.1167 clockwise from (-13.3905, 23) to (-13.7036, 52.7142)
  arc A8 centre (0.0141, 38) radius 22.1167 clockwise from (-16.2386, 23) to (-16.5511, 52.6542)
  circle C7 centre (0, -47) radius 13.55
  circle C8 centre (0, 0) radius 2.4048
  circle C9 centre (-26.2206, 8.558) radius 3
  circle C10 centre (-16, -54) radius 3.25
  arc A9 centre (20, 55) radius 12 clockwise from (20, 67) to (32, 55)
  arc A10 centre (-20, 55) radius 12 clockwise from (-32, 55) to (-20, 67)
  arc A11 centre (-20, -55) radius 12 clockwise from (-20, -67) to (-32, -55)
  arc A12 centre (20, -55) radius 12 clockwise from (32, -55) to (20, -67)
  point P60 (0, 0)
  point P58 (9, 7)
  point P59 (-10, 7)
  horizontal L25
  vertical L26
  horizontal L27
  vertical L28
  dimension "d324" distance L25 P60 = 7
  dimension "d325" distance L27 P60 = 7
  dimension "d326" distance L28 P60 = 10
  dimension "d327" distance P58 P59 = 19
extrude "Extrude1" new body sketch "Sketch10" profile of C8 L25 L26 L27 L28 along normal blind 10.6
sketch "Sketch11" plane through (-9, 0, 0) normal (-1, 0, 0) x axis (0, 0, 1)
  line L1 (-2, 7) -> (-2, -7)
  line L2 (-12.6, 7) -> (-2, 7)
  line L3 (-12.6, -7) -> (-12.6, 7)
  line L4 (-2, -7) -> (-12.6, -7)
  circle C1 centre (-7.0005, 0.0003) radius 2.4998
  circle C2 centre (-7.0005, 0.0003) radius 2.5998
  dimension "d330" = 0.1
extrude "Extrude2" cut sketch "Sketch11" profile of C1 C2 against normal blind 11.1
sketch "Sketch12" plane through (0, 0, -2) normal (0, 0, 1) x axis (1, 0, 0)
  line L1 (10, 7) -> (10, -7)
  line L2 (-9, 7) -> (10, 7)
  line L3 (-9, -7) -> (-9, 7)
  line L4 (10, -7) -> (-9, -7)
  circle C1 centre (0, 0) radius 2.15
  point P1 (0, 0)
  point P6 (0, 0)
  coincident P1 P6
  dimension "d333" diameter C1 = 4.3
sketch "Sketch1" plane through (0, 0, -2) normal (0, 0, 1) x axis (1, 0, 0)
  circle C1 centre (0, 0) radius 2.5
  point P1 (0, 0)
  point P2 (0, 0)
  coincident P1 P2
  dimension "d334" diameter C1 = 5
extrude "Extrude3" cut sketch "Sketch12" profile of C1 against normal blind 7.2
sketch "Sketch2" plane through (0, 0, -2) normal (0, 0, 1) x axis (1, 0, 0)
  line L1 (10, 7) -> (10, -7)
  line L2 (-9, 7) -> (10, 7)
  line L3 (-9, -7) -> (-9, 7)
  line L4 (10, -7) -> (-9, -7)
  circle C1 centre (0, 0) radius 2.15
  circle C2 centre (0, 0) radius 3
  point P1 (0, 0)
  point P7 (0, 0)
  coincident P1 P7
  dimension "d337" diameter C2 = 6
extrude "Extrude4" cut sketch "Sketch2" profile of C1 C2 against normal blind 1.55
delete_face "DeleteFace1"
delete_face "DeleteFace2"
sketch "Sketch3" plane through (0, 0, -12.6) normal (0, 0, -1) x axis (-1, 0, 0)
  line L1 (-10, -7) -> (-10, 7)
  line L2 (9, -7) -> (-10, -7)
  line L3 (9, 7) -> (9, -7)
  line L4 (-10, 7) -> (9, 7)
  line L5 (-4.2597, -8) -> (-4.2597, -3.7691)
  line L6 (-11.8009, -1.25) -> (-7, -1.25)
  circle C1 centre (-7, -4) radius 2.75
  point P7 (-4.2597, -3.7691)
  point P9 (-7, -1.25)
  point P6 (-7, -4)
  coincident C1 P7
  perpendicular L2 L5
  coincident C1 P9
  perpendicular L1 L6
  tangent C1 L6
  dimension "d340" diameter C1 = 5.5
  dimension "d341" distance L1 P6 = 3
  dimension "d342" distance L2 P6 = 3
extrude "Extrude5" cut sketch "Sketch3" profile of L1 L2 C1 L5 L6 against normal blind 3
sketch "Sketch4" plane through (0, 0, -9.6) normal (0, 0, -1) x axis (-1, 0, 0)
  line L1 (-10, -1.25) -> (-7, -1.25)
  line L2 (-10, -7) -> (-10, -1.25)
  line L3 (-4.2597, -7) -> (-10, -7)
  line L4 (-4.2597, -3.7691) -> (-4.2597, -7)
  arc A1 centre (-7, -4) radius 2.75 clockwise from (-7, -1.25) to (-4.2597, -3.7691)
  circle C1 centre (-7, -4) radius 2.75
  circle C2 centre (-7, -4) radius 1.5
  point P3 (-7, -1.25)
  point P2 (-4.2597, -3.7691)
  coincident P3 C1
  coincident P2 C1
  tangent L1 C1
  concentric C1 C2
  dimension "d345" diameter C2 = 3
extrude "Extrude6" cut sketch "Sketch4" profile of C2 against normal blind 10
sketch "Sketch5" plane through (0, 0, -2) normal (0, 0, 1) x axis (1, 0, 0)
  line L1 (10, 7) -> (10, -7)
  line L2 (-9, 7) -> (10, 7)
  line L3 (-9, -7) -> (-9, 7)
  line L4 (10, -7) -> (-9, -7)
  circle C1 centre (7, -4) radius 1.5
  circle C2 centre (0, 0) radius 3
  circle C3 centre (7, 4) radius 1.5
  point P8 (7, 4)
  dimension "d348" diameter C3 = 3
  dimension "d349" distance L2 P8 = 3
extrude "Extrude7" cut sketch "Sketch5" profile of C3 against normal blind 4
sketch "Sketch20" plane through (0, 0, -2) normal (0, 0, -1) x axis (-1, 0, 0)
  line L1 (12.455, -23.788) -> (12.455, -10.688)
  line L2 (-10.455, -25.788) -> (10.455, -25.788)
  line L3 (-12.455, -10.688) -> (-12.455, -23.788)
  line L4 (10.455, -8.688) -> (-10.455, -8.688)
  line L5 (15.947, 53.3392) -> (13.0996, 53.2792)
  line L6 (13.4186, 23) -> (16.2667, 23)
  line L7 (-13.7036, 52.7142) -> (-16.5511, 52.6542)
  line L8 (-16.2386, 23) -> (-13.3905, 23)
  line L9 (32, 14) -> (26.5417, 14)
  line L10 (32, 55) -> (32, 14)
  line L11 (-20, 67) -> (20, 67)
  line L12 (-32, 25) -> (-32, 55)
  line L13 (-26.7827, 25) -> (-32, 25)
  line L14 (-26.7827, 21) -> (-26.7827, 25)
  line L15 (-32, 21) -> (-26.7827, 21)
  line L16 (-32, -4) -> (-32, 21)
  line L17 (-26.671, -4) -> (-32, -4)
  line L18 (-26.7827, -8) -> (-26.671, -4)
  line L19 (-32, -8) -> (-26.7827, -8)
  line L20 (-32, -55) -> (-32, -8)
  line L21 (20, -67) -> (-20, -67)
  line L22 (32, 10) -> (32, -55)
  line L23 (26.5417, 10) -> (32, 10)
  line L24 (26.5417, 14) -> (26.5417, 10)
  circle C1 centre (16, -40) radius 3.25
  circle C2 centre (22, -50) radius 3.0946
  circle C3 centre (-21.5, 24) radius 3
  arc A1 centre (10.455, -23.788) radius 2 clockwise from (12.455, -23.788) to (10.455, -25.788)
  arc A2 centre (-10.455, -23.788) radius 2 clockwise from (-10.455, -25.788) to (-12.455, -23.788)
  arc A3 centre (-10.455, -10.688) radius 2 clockwise from (-12.455, -10.688) to (-10.455, -8.688)
  arc A4 centre (10.455, -10.688) radius 2 clockwise from (10.455, -8.688) to (12.455, -10.688)
  circle C4 centre (0.0141, 38) radius 18
  circle C5 centre (0.0009, 14.35) radius 1.55
  circle C6 centre (-0.001, 61.6494) radius 1.5503
  arc A5 centre (0.0141, 38) radius 22.1167 clockwise from (15.947, 53.3392) to (16.2667, 23)
  arc A6 centre (0.0141, 38) radius 20.1167 clockwise from (13.0996, 53.2792) to (13.4186, 23)
  arc A7 centre (0.0141, 38) radius 20.1167 clockwise from (-13.3905, 23) to (-13.7036, 52.7142)
  arc A8 centre (0.0141, 38) radius 22.1167 clockwise from (-16.2386, 23) to (-16.5511, 52.6542)
  circle C7 centre (0, -47) radius 13.55
  circle C8 centre (0, 0) radius 2.4048
  circle C9 centre (-26.2206, 8.558) radius 3
  circle C10 centre (-16, -54) radius 3.25
  arc A9 centre (20, 55) radius 12 clockwise from (20, 67) to (32, 55)
  arc A10 centre (-20, 55) radius 12 clockwise from (-32, 55) to (-20, 67)
  arc A11 centre (-20, -55) radius 12 clockwise from (-20, -67) to (-32, -55)
  arc A12 centre (20, -55) radius 12 clockwise from (32, -55) to (20, -67)
  circle C11 centre (-7, -4) radius 3
  dimension "d352" diameter C11 = 6
extrude "Extrude20" add sketch "Sketch20" profile of C11 along normal blind 3
sketch "Sketch21" plane through (0, 0, -5) normal (0, 0, -1) x axis (-1, 0, 0)
  circle C1 centre (-7, -4) radius 3
  circle C2 centre (-7, -4) radius 1
  concentric C1 C2
  dimension "d355" diameter C2 = 2
extrude "Extrude21" cut sketch "Sketch21" profile of C2 against normal blind 4
sketch "Sketch6" plane through (0, 0, -2) normal (0, 0, 1) x axis (1, 0, 0)
  line L1 (10, 7) -> (10, -7)
  line L2 (-9, 7) -> (10, 7)
  line L3 (-9, -7) -> (-9, 7)
  line L4 (10, -7) -> (-9, -7)
  line L5 (3.5, -7) -> (10, -7)
  line L6 (3.5, -0.5) -> (3.5, -7)
  line L7 (10, -0.5) -> (3.5, -0.5)
  line L8 (10, -7) -> (10, -0.5)
  circle C1 centre (7, 4) radius 1.5
  circle C2 centre (7, -4) radius 1.5
  circle C3 centre (0, 0) radius 3
  point P5 (10, -7)
  point P9 (10, -7)
  point P10 (3.5, -7)
  point P12 (10, -0.5)
  horizontal L5
  vertical L6
  horizontal L7
  vertical L8
  coincident P5 P9
  dimension "d358" distance P9 P10 = 6.5
  dimension "d359" distance P9 P12 = 6.5
extrude "Extrude8" cut sketch "Sketch6" profile of C2 L1 L4 L5 L6 L7 L8 against normal blind 3.3
fillet "Fillet1" radius 2.75
fillet "Fillet2" radius 3.25
fillet "Fillet3" radius 2.25
fillet "Fillet4" radius 2.75 2.75
sketch "Sketch22" plane through (0, 0, -2) normal (0, 0, -1) x axis (-1, 0, 0)
  line L1 (32, 14) -> (26.5417, 14)
  line L2 (32, 55) -> (32, 14)
  line L3 (-20, 67) -> (20, 67)
  line L4 (-32, 25) -> (-32, 55)
  line L5 (-26.7827, 25) -> (-32, 25)
  line L6 (-26.7827, 21) -> (-26.7827, 25)
  line L7 (-32, 21) -> (-26.7827, 21)
  line L8 (-32, -4) -> (-32, 21)
  line L9 (-26.671, -4) -> (-32, -4)
  line L10 (-26.7827, -8) -> (-26.671, -4)
  line L11 (-32, -8) -> (-26.7827, -8)
  line L12 (-32, -55) -> (-32, -8)
  line L13 (20, -67) -> (-20, -67)
  line L14 (32, 10) -> (32, -55)
  line L15 (26.5417, 10) -> (32, 10)
  line L16 (26.5417, 14) -> (26.5417, 10)
  line L17 (-13.7036, 52.7142) -> (-16.5511, 52.6542)
  line L18 (-16.2386, 23) -> (-13.3905, 23)
  line L19 (15.947, 53.3392) -> (13.0996, 53.2792)
  line L20 (13.4186, 23) -> (16.2667, 23)
  line L21 (12.455, -23.788) -> (12.455, -10.688)
  line L22 (-10.455, -25.788) -> (10.455, -25.788)
  line L23 (-12.455, -10.688) -> (-12.455, -23.788)
  line L24 (10.455, -8.688) -> (-10.455, -8.688)
  arc A1 centre (20, 55) radius 12 clockwise from (20, 67) to (32, 55)
  arc A2 centre (-20, 55) radius 12 clockwise from (-32, 55) to (-20, 67)
  arc A3 centre (-20, -55) radius 12 clockwise from (-20, -67) to (-32, -55)
  arc A4 centre (20, -55) radius 12 clockwise from (32, -55) to (20, -67)
  circle C1 centre (-16, -54) radius 3.25
  circle C2 centre (-26.2206, 8.558) radius 3
  circle C3 centre (0, 0) radius 2.4048
  circle C4 centre (0, -47) radius 13.55
  arc A5 centre (0.0141, 38) radius 20.1167 clockwise from (-13.3905, 23) to (-13.7036, 52.7142)
  arc A6 centre (0.0141, 38) radius 22.1167 clockwise from (-16.2386, 23) to (-16.5511, 52.6542)
  arc A7 centre (0.0141, 38) radius 22.1167 clockwise from (15.947, 53.3392) to (16.2667, 23)
  arc A8 centre (0.0141, 38) radius 20.1167 clockwise from (13.0996, 53.2792) to (13.4186, 23)
  circle C5 centre (-0.001, 61.6494) radius 1.5503
  circle C6 centre (0.0009, 14.35) radius 1.55
  circle C7 centre (0.0141, 38) radius 18
  arc A9 centre (10.455, -23.788) radius 2 clockwise from (12.455, -23.788) to (10.455, -25.788)
  arc A10 centre (-10.455, -23.788) radius 2 clockwise from (-10.455, -25.788) to (-12.455, -23.788)
  arc A11 centre (-10.455, -10.688) radius 2 clockwise from (-12.455, -10.688) to (-10.455, -8.688)
  arc A12 centre (10.455, -10.688) radius 2 clockwise from (10.455, -8.688) to (12.455, -10.688)
  circle C8 centre (-21.5, 24) radius 3
  circle C9 centre (22, -50) radius 3.0946
  circle C10 centre (16, -40) radius 3.25
  circle C11 centre (-7, -4) radius 3
  circle C12 centre (-7, 4) radius 1.4
  dimension "d372" diameter C12 = 2.8
extrude "Extrude22" add sketch "Sketch22" profile of C12 along normal blind 3.7
fillet "Fillet4" radius 0.5
chamfer "Chamfer5" distance 0.5
chamfer "Chamfer6" distance 0.5
chamfer "Chamfer7" distance 0.5
chamfer "Chamfer8" distance 0.4
fillet "Fillet5" radius 1
chamfer "Chamfer9" distance 0.5
chamfer "Chamfer10" distance 0.5
fillet "Fillet6" radius 1
position "Position8"
move_face "MoveFace1"
position "Position9"
move_face "MoveFace1"
sketch "Sketch12" plane through (0, 0, -15.4579) normal (0, 0, 1) x axis (1, 0, 0)
  line L1 (21.3, 19.0732) -> (21.3, 19.9132)
  line L2 (26.9755, 19.0732) -> (21.3, 19.0732)
  line L3 (26.9755, 22.3732) -> (26.9755, 19.0732)
  line L4 (16.9755, 22.3732) -> (26.9755, 22.3732)
  line L5 (16.9755, 19.9132) -> (16.9755, 22.3732)
  line L6 (21.3, 19.9132) -> (16.9755, 19.9132)
  line L7 (28.0412, 17.6522) -> (15.448, 17.6522)
  line L8 (28.0412, 27.4357) -> (28.0412, 17.6522)
  line L9 (15.448, 27.4357) -> (28.0412, 27.4357)
  line L10 (15.448, 17.6522) -> (15.448, 27.4357)
  horizontal L7
  vertical L8
  horizontal L9
  vertical L10
extrude "Extrude13" cut sketch "Sketch12" profile of L1 L2 L3 L4 L6 L7 L8 L9 L10 along normal blind 4
sketch "Sketch13" plane through (0, 0, -15.4579) normal (0, 0, 1) x axis (1, 0, 0)
  line L1 (21.3, 19.0732) -> (21.3, 19.9132)
  line L2 (26.9755, 19.0732) -> (21.3, 19.0732)
  line L3 (26.9755, 27.0732) -> (26.9755, 19.0732)
  line L4 (16.9755, 27.0732) -> (26.9755, 27.0732)
  line L5 (16.9755, 19.9132) -> (16.9755, 27.0732)
  line L6 (21.3, 19.9132) -> (16.9755, 19.9132)
  line L7 (27.5613, 28.3735) -> (15.0448, 28.3735)
  line L8 (27.5613, 21.9787) -> (27.5613, 28.3735)
  line L9 (15.0448, 21.9787) -> (27.5613, 21.9787)
  line L10 (15.0448, 28.3735) -> (15.0448, 21.9787)
  horizontal L7
  vertical L8
  horizontal L9
  vertical L10
sketch "Sketch13" plane through (0, 0, -15.4579) normal (0, 0, 1) x axis (1, 0, 0)
  line L1 (21.3, 19.0732) -> (21.3, 19.9132)
  line L2 (26.9755, 19.0732) -> (21.3, 19.0732)
  line L3 (26.9755, 27.0732) -> (26.9755, 19.0732)
  line L4 (16.9755, 27.0732) -> (26.9755, 27.0732)
  line L5 (16.9755, 19.9132) -> (16.9755, 27.0732)
  line L6 (21.3, 19.9132) -> (16.9755, 19.9132)
  line L7 (26.9755, 27.6187) -> (14.9014, 27.6187)
  line L8 (26.9755, 22) -> (26.9755, 27.6187)
  line L9 (14.9014, 22) -> (26.9755, 22)
  line L10 (14.9014, 27.6187) -> (14.9014, 22)
  point P10 (26.9755, 22)
  horizontal L7
  vertical L8
  horizontal L9
  vertical L10
  coincident L3 P10
extrude "Extrude14" cut sketch "Sketch13" profile of L3 L4 L5 L8 L9 against normal blind 1.142 (magnitude of "-6.5 mm - 0.042 mm + 5.4 mm")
